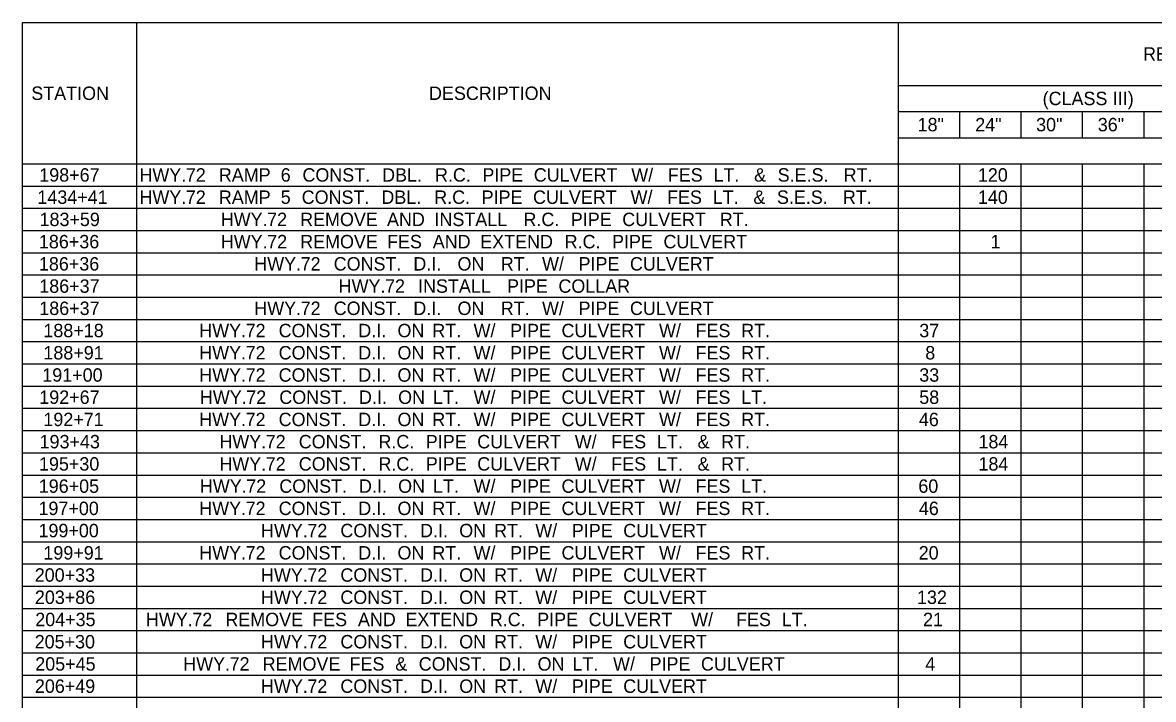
# Model space of a CAD drawing. Extents: x 1226561 to 1228164, y 151309 to 152305.
# Drawn here: x 1226564.7 to 1226933.4, y 152044.7 to 152265.3 of the extents above; entities that cross this region are included whole.
import ezdxf

# ---------------------------------------------------------------- set-up
doc = ezdxf.new("R2010")
doc.units = 0
doc.layers.add('R_Dimension', color=7, linetype='Continuous')

msp = doc.modelspace()

# ---------------------------------------------------------------- linework, layer by layer
at = {"layer": 'R_Dimension'}
for p, q in [((1226564.67, 152265.3), (1228152.39, 152265.3)), ((1226564.67, 151874.5), (1226564.67, 152265.3)), ((1226601.93, 151950.78), (1226601.93, 152265.3)), ((1226850.27, 151874.5), (1226850.27, 152265.3)), ((1226850.27, 152244.85), (1227116.78, 152244.85)), ((1226850.27, 152236.32), (1227335.26, 152236.32)), ((1226870.3, 152227.8), (1226870.3, 152236.32)), ((1226890.33, 152227.8), (1226890.33, 152236.32)), ((1226910.36, 152227.8), (1226910.36, 152236.32)), ((1226930.39, 152227.8), (1226930.39, 152236.32)), ((1226850.27, 152227.8), (1228152.39, 152227.8)), ((1226564.67, 152219.27), (1228152.39, 152219.27)), ((1226870.3, 151874.5), (1226870.3, 152219.27)), ((1226890.33, 151874.5), (1226890.33, 152219.27)), ((1226910.36, 151874.5), (1226910.36, 152219.27)), ((1226930.39, 151874.5), (1226930.39, 152219.27)), ((1226564.67, 152212.03), (1228152.39, 152212.03)), ((1226564.67, 152204.78), (1228152.39, 152204.78)), ((1226564.67, 152197.54), (1228152.39, 152197.54)), ((1226564.67, 152190.29), (1228152.39, 152190.29)), ((1226564.67, 152183.05), (1228152.39, 152183.05)), ((1226564.67, 152175.8), (1228152.39, 152175.8)), ((1226564.67, 152168.56), (1228152.39, 152168.56)), ((1226564.67, 152161.31), (1228152.39, 152161.31)), ((1226564.67, 152154.07), (1228152.39, 152154.07)), ((1226564.67, 152146.82), (1228152.39, 152146.82)), ((1226564.67, 152139.58), (1228152.39, 152139.58)), ((1226564.67, 152132.33), (1228152.39, 152132.33)), ((1226564.67, 152125.09), (1228152.39, 152125.09)), ((1226564.67, 152117.84), (1228152.39, 152117.84)), ((1226564.67, 152110.6), (1228152.39, 152110.6)), ((1226564.67, 152103.35), (1228152.39, 152103.35)), ((1226564.67, 152096.11), (1228152.39, 152096.11)), ((1226564.67, 152088.86), (1228152.39, 152088.86)), ((1226564.67, 152081.62), (1228152.39, 152081.62)), ((1226564.67, 152074.37), (1228152.39, 152074.37)), ((1226564.67, 152067.13), (1228152.39, 152067.13)), ((1226564.67, 152059.88), (1228152.39, 152059.88)), ((1226564.67, 152052.64), (1228152.39, 152052.64)), ((1226564.67, 152045.39), (1228152.39, 152045.39))]:
    msp.add_line(p, q, dxfattribs=at)

# ---------------------------------------------------------------- texts
for s, height, p in [('REINFORCED', 4.371, (1226930.07, 152252.89)), ('STATION', 4.371, (1226567.51, 152240.1)), ('DESCRIPTION', 4.3711, (1226697.21, 152240.1)), ('(CLASS', 4.371, (1226897.32, 152238.4)), (' III)', 4.371, (1226918.59, 152238.4)), ('18"', 4.371, (1226856.55, 152229.87)), ('24"', 4.371, (1226875.34, 152229.87)), ('30"', 4.371, (1226895.2, 152229.87)), ('36"', 4.371, (1226915.3, 152229.87)), ('198+67', 4.371, (1226570.11, 152213.47)), ('HWY.', 4.371, (1226602.78, 152213.47)), (' 72', 4.371, (1226616.27, 152213.47)), (' RAMP', 4.371, (1226627.05, 152213.47)), (' 6', 4.371, (1226647.22, 152213.47)), (' CONST.', 4.371, (1226654.31, 152213.47)), (' DBL.', 4.371, (1226680.29, 152213.47)), (' R.C.', 4.371, (1226697.53, 152213.47)), (' PIPE', 4.371, (1226712.99, 152213.47)), (' CULVERT', 4.371, (1226729.75, 152213.47)), (' W/', 4.371, (1226761.55, 152213.47)), (' FES', 4.371, (1226773.46, 152213.47)), (' LT.', 4.371, (1226788.36, 152213.47)), (' &', 4.371, (1226801.61, 152213.47)), (' S.E.S.', 4.371, (1226809.29, 152213.47)), (' RT.', 4.371, (1226830.8, 152213.47)), ('120', 4.371, (1226876.2, 152213.47)), ('1434+41', 4.371, (1226569.49, 152206.22)), ('HWY.', 4.371, (1226602.78, 152206.22)), (' 72', 4.371, (1226616.27, 152206.22)), (' RAMP', 4.371, (1226627.05, 152206.22)), (' 5', 4.371, (1226647.22, 152206.22)), (' CONST.', 4.371, (1226654.06, 152206.22)), (' DBL.', 4.371, (1226680.05, 152206.22)), (' R.C.', 4.371, (1226697.29, 152206.22)), (' PIPE', 4.371, (1226712.75, 152206.22)), (' CULVERT', 4.371, (1226729.51, 152206.22)), (' W/', 4.371, (1226761.31, 152206.22)), (' FES', 4.371, (1226773.22, 152206.22)), (' LT.', 4.371, (1226788.12, 152206.22)), (' &', 4.371, (1226801.37, 152206.22)), (' S.E.S.', 4.371, (1226809.05, 152206.22)), (' RT.', 4.371, (1226830.56, 152206.22)), ('140', 4.371, (1226876.2, 152206.22)), ('183+59', 4.371, (1226570.2, 152198.98)), ('HWY.', 4.371, (1226629.29, 152198.98)), (' 72', 4.371, (1226642.78, 152198.98)), (' REMOVE', 4.371, (1226653.55, 152198.98)), (' AND', 4.371, (1226681.88, 152198.98)), (' INSTALL', 4.371, (1226697.37, 152198.98)), (' R.C.', 4.371, (1226726.38, 152198.98)), (' PIPE', 4.371, (1226741.83, 152198.98)), (' CULVERT', 4.371, (1226758.6, 152198.98)), (' RT.', 4.371, (1226790.4, 152198.98)), ('186+36', 4.371, (1226569.99, 152191.73)), ('HWY.', 4.371, (1226629.31, 152191.73)), (' 72', 4.371, (1226642.8, 152191.73)), (' REMOVE', 4.371, (1226653.57, 152191.73)), (' FES', 4.371, (1226681.9, 152191.73)), (' AND', 4.371, (1226696.8, 152191.73)), (' EXTEND', 4.371, (1226712.29, 152191.73)), (' R.C.', 4.371, (1226739.82, 152191.73)), (' PIPE', 4.371, (1226755.27, 152191.73)), (' CULVERT', 4.371, (1226772.04, 152191.73)), ('1', 4.37, (1226880.32, 152191.73)), ('186+36', 4.371, (1226569.99, 152184.49)), ('HWY.', 4.371, (1226640.23, 152184.49)), (' 72', 4.371, (1226653.72, 152184.49)), (' CONST.', 4.371, (1226664.5, 152184.49)), (' D.I.', 4.371, (1226690.48, 152184.49)), ('  ON', 4.371, (1226703.25, 152184.49)), (' RT.', 4.371, (1226718.98, 152184.49)), (' W/', 4.371, (1226732.44, 152184.49)), (' PIPE', 4.371, (1226744.35, 152184.49)), (' CULVERT', 4.371, (1226761.11, 152184.49)), ('186+37', 4.371, (1226570.11, 152177.24)), ('HWY.', 4.371, (1226667.75, 152177.24)), (' 72', 4.371, (1226681.24, 152177.24)), (' INSTALL', 4.371, (1226692.01, 152177.24)), (' PIPE', 4.371, (1226721.03, 152177.24)), (' COLLAR', 4.371, (1226737.79, 152177.24)), ('186+37', 4.371, (1226570.11, 152170)), ('HWY.', 4.371, (1226640.23, 152170)), (' 72', 4.371, (1226653.72, 152170)), (' CONST.', 4.371, (1226664.5, 152170)), (' D.I.', 4.371, (1226690.48, 152170)), ('  ON', 4.371, (1226703.25, 152170)), (' RT.', 4.371, (1226718.98, 152170)), (' W/', 4.371, (1226732.44, 152170)), (' PIPE', 4.371, (1226744.35, 152170)), (' CULVERT', 4.371, (1226761.11, 152170)), (' W/', 4.371, (1226710.12, 152162.75)), (' W/', 4.371, (1226770.59, 152162.75)), ('188+18', 4.371, (1226571.45, 152162.75)), ('HWY.', 4.371, (1226622.28, 152162.75)), (' 72', 4.371, (1226635.78, 152162.75)), (' CONST.', 4.371, (1226646.55, 152162.75)), (' D.I.', 4.371, (1226672.53, 152162.75)), (' ON', 4.371, (1226685.3, 152162.75)), (' RT.', 4.371, (1226696.66, 152162.75)), (' PIPE', 4.371, (1226722.03, 152162.75)), (' CULVERT', 4.371, (1226738.79, 152162.75)), (' FES', 4.371, (1226782.5, 152162.75)), (' RT.', 4.371, (1226797.4, 152162.75)), ('37', 4.371, (1226857.09, 152162.75)), ('188+91', 4.371, (1226571.45, 152155.51)), (' 72', 4.371, (1226635.78, 152155.51)), (' CONST.', 4.371, (1226646.55, 152155.51)), (' ON', 4.371, (1226685.3, 152155.51)), (' W/', 4.371, (1226710.12, 152155.51)), (' CULVERT', 4.371, (1226738.79, 152155.51)), (' W/', 4.371, (1226770.59, 152155.51)), (' FES', 4.371, (1226782.5, 152155.51)), ('8', 4.37, (1226859.05, 152155.51)), ('HWY.', 4.371, (1226622.28, 152155.51)), (' D.I.', 4.371, (1226672.53, 152155.51)), (' RT.', 4.371, (1226696.66, 152155.51)), (' PIPE', 4.371, (1226722.03, 152155.51)), (' RT.', 4.371, (1226797.4, 152155.51)), ('191+00', 4.371, (1226571.09, 152148.26)), ('HWY.', 4.371, (1226622.28, 152148.26)), (' 72', 4.371, (1226635.78, 152148.26)), (' CONST.', 4.371, (1226646.55, 152148.26)), (' D.I.', 4.371, (1226672.53, 152148.26)), (' ON', 4.371, (1226685.3, 152148.26)), (' RT.', 4.371, (1226696.66, 152148.26)), (' W/', 4.371, (1226710.12, 152148.26)), (' PIPE', 4.371, (1226722.03, 152148.26)), (' CULVERT', 4.371, (1226738.79, 152148.26)), (' W/', 4.371, (1226770.59, 152148.26)), (' FES', 4.371, (1226782.5, 152148.26)), (' RT.', 4.371, (1226797.4, 152148.26)), ('33', 4.371, (1226857.09, 152148.26)), ('192+67', 4.371, (1226570.11, 152141.02)), ('HWY.', 4.371, (1226622.49, 152141.02)), (' 72', 4.371, (1226635.98, 152141.02)), (' CONST.', 4.371, (1226646.76, 152141.02)), (' D.I.', 4.371, (1226672.74, 152141.02)), (' ON', 4.371, (1226685.51, 152141.02)), (' LT.', 4.371, (1226696.87, 152141.02)), (' W/', 4.371, (1226710.12, 152141.02)), (' PIPE', 4.371, (1226722.03, 152141.02)), (' CULVERT', 4.371, (1226738.79, 152141.02)), (' W/', 4.371, (1226770.59, 152141.02)), (' FES', 4.371, (1226782.5, 152141.02)), (' LT.', 4.371, (1226797.4, 152141.02)), ('58', 4.371, (1226857.09, 152141.02)), ('192+71', 4.371, (1226571.45, 152133.77)), ('HWY.', 4.371, (1226622.28, 152133.77)), (' 72', 4.371, (1226635.78, 152133.77)), (' CONST.', 4.371, (1226646.55, 152133.77)), (' D.I.', 4.371, (1226672.53, 152133.77)), (' ON', 4.371, (1226685.3, 152133.77)), (' RT.', 4.371, (1226696.66, 152133.77)), (' W/', 4.371, (1226710.12, 152133.77)), (' PIPE', 4.371, (1226722.03, 152133.77)), (' CULVERT', 4.371, (1226738.79, 152133.77)), (' W/', 4.371, (1226770.59, 152133.77)), (' FES', 4.371, (1226782.5, 152133.77)), (' RT.', 4.371, (1226797.4, 152133.77)), ('46', 4.371, (1226856.96, 152133.77)), ('193+43', 4.371, (1226570.21, 152126.53)), ('HWY.', 4.371, (1226628.84, 152126.53)), (' 72', 4.371, (1226642.33, 152126.53)), (' CONST.', 4.371, (1226653.11, 152126.53)), (' R.C.', 4.371, (1226679.09, 152126.53)), (' PIPE', 4.371, (1226694.54, 152126.53)), (' CULVERT', 4.371, (1226711.31, 152126.53)), (' W/', 4.371, (1226743.11, 152126.53)), (' FES', 4.371, (1226755.02, 152126.53)), (' LT.', 4.371, (1226769.92, 152126.53)), (' &', 4.371, (1226783.17, 152126.53)), (' RT.', 4.371, (1226790.85, 152126.53)), ('184', 4.371, (1226876.39, 152126.53)), ('195+30', 4.371, (1226570.02, 152119.28)), ('HWY.', 4.371, (1226628.84, 152119.28)), (' 72', 4.371, (1226642.33, 152119.28)), (' CONST.', 4.371, (1226653.11, 152119.28)), (' R.C.', 4.371, (1226679.09, 152119.28)), (' PIPE', 4.371, (1226694.54, 152119.28)), (' CULVERT', 4.371, (1226711.31, 152119.28)), (' W/', 4.371, (1226743.11, 152119.28)), (' FES', 4.371, (1226755.02, 152119.28)), (' LT.', 4.371, (1226769.92, 152119.28)), (' &', 4.371, (1226783.17, 152119.28)), (' RT.', 4.371, (1226790.85, 152119.28)), ('184', 4.371, (1226876.39, 152119.28)), ('196+05', 4.371, (1226569.94, 152112.04)), ('HWY.', 4.371, (1226622.49, 152112.04)), (' 72', 4.371, (1226635.98, 152112.04)), (' CONST.', 4.371, (1226646.76, 152112.04)), (' D.I.', 4.371, (1226672.74, 152112.04)), (' ON', 4.371, (1226685.51, 152112.04)), (' LT.', 4.371, (1226696.87, 152112.04)), (' W/', 4.371, (1226710.12, 152112.04)), (' PIPE', 4.371, (1226722.03, 152112.04)), (' CULVERT', 4.371, (1226738.79, 152112.04)), (' W/', 4.371, (1226770.59, 152112.04)), (' FES', 4.371, (1226782.5, 152112.04)), (' LT.', 4.371, (1226797.4, 152112.04)), ('60', 4.371, (1226856.79, 152112.04)), ('197+00', 4.371, (1226569.85, 152104.79)), ('HWY.', 4.371, (1226622.28, 152104.79)), (' 72', 4.371, (1226635.78, 152104.79)), (' CONST.', 4.371, (1226646.55, 152104.79)), (' D.I.', 4.371, (1226672.53, 152104.79)), (' ON', 4.371, (1226685.3, 152104.79)), (' RT.', 4.371, (1226696.66, 152104.79)), (' W/', 4.371, (1226710.12, 152104.79)), (' PIPE', 4.371, (1226722.03, 152104.79)), (' CULVERT', 4.371, (1226738.79, 152104.79)), (' W/', 4.371, (1226770.59, 152104.79)), (' FES', 4.371, (1226782.5, 152104.79)), (' RT.', 4.371, (1226797.4, 152104.79)), ('46', 4.371, (1226856.96, 152104.79)), ('199+00', 4.371, (1226569.85, 152097.55)), ('HWY.', 4.371, (1226642.42, 152097.55)), (' 72', 4.371, (1226655.91, 152097.55)), (' CONST.', 4.371, (1226666.68, 152097.55)), (' D.I.', 4.371, (1226692.67, 152097.55)), (' ON', 4.371, (1226705.44, 152097.55)), (' RT.', 4.371, (1226716.8, 152097.55)), (' W/', 4.371, (1226730.25, 152097.55)), (' PIPE', 4.371, (1226742.16, 152097.55)), (' CULVERT', 4.371, (1226758.92, 152097.55)), ('199+91', 4.371, (1226571.45, 152090.3)), ('HWY.', 4.371, (1226622.28, 152090.3)), (' 72', 4.371, (1226635.78, 152090.3)), (' CONST.', 4.371, (1226646.55, 152090.3)), (' D.I.', 4.371, (1226672.53, 152090.3)), (' ON', 4.371, (1226685.3, 152090.3)), (' RT.', 4.371, (1226696.66, 152090.3)), (' W/', 4.371, (1226710.12, 152090.3)), (' PIPE', 4.371, (1226722.03, 152090.3)), (' CULVERT', 4.371, (1226738.79, 152090.3)), (' W/', 4.371, (1226770.59, 152090.3)), (' FES', 4.371, (1226782.5, 152090.3)), (' RT.', 4.371, (1226797.4, 152090.3)), ('20', 4.371, (1226856.9, 152090.3)), ('200+33', 4.371, (1226568.63, 152083.06)), ('HWY.', 4.371, (1226642.42, 152083.06)), (' 72', 4.371, (1226655.91, 152083.06)), (' CONST.', 4.371, (1226666.68, 152083.06)), (' D.I.', 4.371, (1226692.67, 152083.06)), (' ON', 4.371, (1226705.44, 152083.06)), (' RT.', 4.371, (1226716.8, 152083.06)), (' W/', 4.371, (1226730.25, 152083.06)), (' PIPE', 4.371, (1226742.16, 152083.06)), (' CULVERT', 4.371, (1226758.92, 152083.06)), ('203+86', 4.371, (1226568.68, 152075.81)), ('HWY.', 4.371, (1226642.42, 152075.81)), (' 72', 4.371, (1226655.91, 152075.81)), (' CONST.', 4.371, (1226666.68, 152075.81)), (' D.I.', 4.371, (1226692.67, 152075.81)), (' ON', 4.371, (1226705.44, 152075.81)), (' RT.', 4.371, (1226716.8, 152075.81)), (' W/', 4.371, (1226730.25, 152075.81)), (' PIPE', 4.371, (1226742.16, 152075.81)), (' CULVERT', 4.371, (1226758.92, 152075.81)), ('132', 4.371, (1226856.36, 152075.81)), ('204+35', 4.371, (1226568.8, 152068.57)), ('HWY.', 4.371, (1226604.9, 152068.57)), (' 72', 4.371, (1226618.39, 152068.57)), (' REMOVE', 4.371, (1226629.17, 152068.57)), (' FES', 4.371, (1226657.49, 152068.57)), (' AND', 4.371, (1226672.4, 152068.57)), (' EXTEND', 4.371, (1226687.88, 152068.57)), (' R.C.', 4.371, (1226715.42, 152068.57)), (' PIPE', 4.371, (1226730.87, 152068.57)), (' CULVERT', 4.371, (1226747.63, 152068.57)), ('  W/', 4.371, (1226779.44, 152068.57)), (' FES', 4.371, (1226795.72, 152068.57)), (' LT.', 4.371, (1226810.62, 152068.57)), ('21', 4.371, (1226858.32, 152068.57)), ('205+30', 4.371, (1226568.61, 152061.32)), ('HWY.', 4.371, (1226642.42, 152061.32)), (' 72', 4.371, (1226655.91, 152061.32)), (' CONST.', 4.371, (1226666.68, 152061.32)), (' D.I.', 4.371, (1226692.67, 152061.32)), (' ON', 4.371, (1226705.44, 152061.32)), (' RT.', 4.371, (1226716.8, 152061.32)), (' W/', 4.371, (1226730.25, 152061.32)), (' PIPE', 4.371, (1226742.16, 152061.32)), (' CULVERT', 4.371, (1226758.92, 152061.32)), ('205+45', 4.371, (1226568.8, 152054.08)), ('HWY.', 4.371, (1226617.07, 152054.08)), (' 72', 4.371, (1226630.56, 152054.08)), (' REMOVE', 4.371, (1226641.33, 152054.08)), (' FES', 4.371, (1226669.66, 152054.08)), (' &', 4.371, (1226684.56, 152054.08)), (' CONST.', 4.371, (1226692.24, 152054.08)), (' D.I.', 4.371, (1226718.22, 152054.08)), (' ON', 4.371, (1226730.99, 152054.08)), (' LT.', 4.371, (1226742.35, 152054.08)), (' W/', 4.371, (1226755.6, 152054.08)), (' PIPE', 4.371, (1226767.51, 152054.08)), (' CULVERT', 4.371, (1226784.27, 152054.08)), ('4', 4.37, (1226859.05, 152054.08)), ('206+49', 4.371, (1226568.68, 152046.83)), ('HWY.', 4.371, (1226642.42, 152046.83)), (' 72', 4.371, (1226655.91, 152046.83)), (' CONST.', 4.371, (1226666.68, 152046.83)), (' D.I.', 4.371, (1226692.67, 152046.83)), (' ON', 4.371, (1226705.44, 152046.83)), (' RT.', 4.371, (1226716.8, 152046.83)), (' W/', 4.371, (1226730.25, 152046.83)), (' PIPE', 4.371, (1226742.16, 152046.83)), (' CULVERT', 4.371, (1226758.92, 152046.83))]:
    msp.add_text(s, height=height, dxfattribs=at).set_placement(p)

doc.saveas('drawing.dxf')
